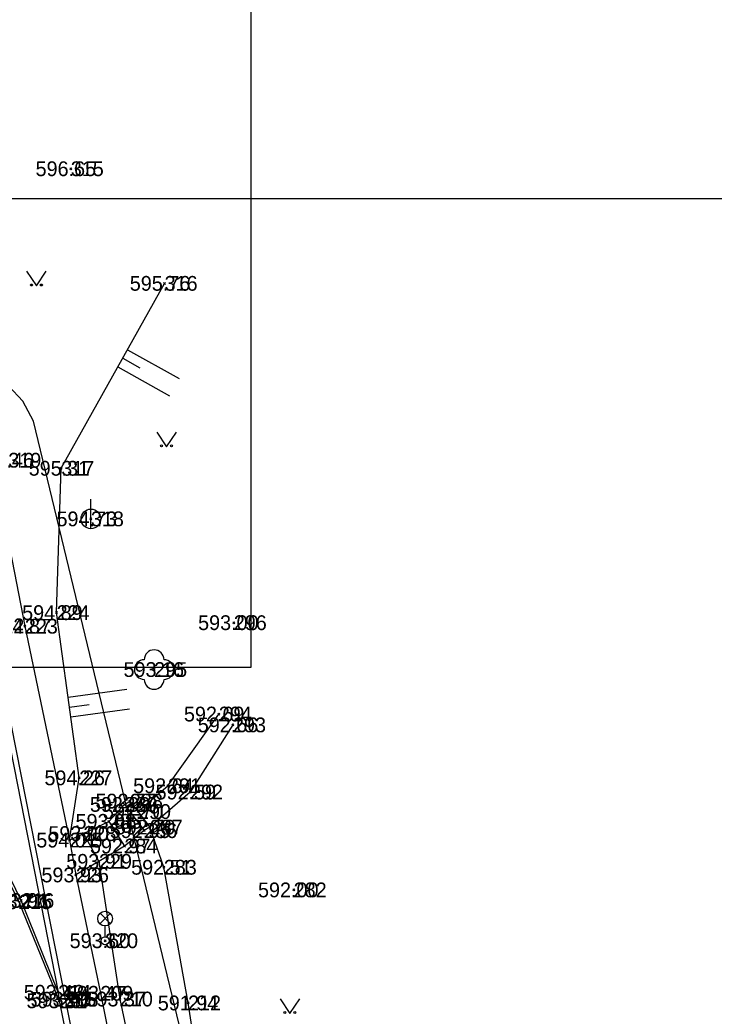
# Model space of a CAD drawing. Extents: x -844765 to -843273, y -997542 to -995529.
# Drawn here: x -843394.4 to -843359.2, y -997393 to -997342.4 of the extents above; entities that cross this region are included whole.
import ezdxf

# ---------------------------------------------------------------- set-up
doc = ezdxf.new("R2010")
doc.units = 0
for name, color, linetype in [('Betonový strop', 7, 'Continuous'), ('Dno', 7, 'Continuous'), ('Doplněk polohopisu', 7, 'Continuous'), ('Groma', 7, 'Continuous'), ('Osa', 7, 'Continuous'), ('Přítoky', 7, 'Continuous'), ('Sítě podzemní nerozlišené', 7, 'Continuous'), ('Vrstva 63', 7, 'Continuous'), ('Výškopis', 7, 'Continuous'), ('Číslo bodu', 7, 'Continuous'), ('Řezy', 7, 'Continuous')]:
    doc.layers.add(name, color=color, linetype=linetype)

msp = doc.modelspace()

# ---------------------------------------------------------------- linework, layer by layer
at = {"layer": 'Betonový strop'}
for points in [[(-843411.04, -997345.91), (-843412.15, -997348.62), (-843412.25, -997350.69), (-843411.88, -997353.72), (-843411.81, -997353.92), (-843411.14, -997356.34), (-843411.1, -997356.6), (-843409.66, -997360.3), (-843407.54, -997364.86), (-843405.52, -997368.28), (-843401.64, -997374.1), (-843397.84, -997380.36), (-843394.46, -997387.21), (-843392.42, -997392.24)], [(-843392.47, -997391.81), (-843394.34, -997387.15), (-843397.7, -997380.27), (-843401.51, -997374.02), (-843405.41, -997368.2), (-843407.39, -997364.76), (-843409.55, -997360.23), (-843410.95, -997356.55), (-843410.97, -997356.46), (-843411.8, -997353.57), (-843412.09, -997350.7), (-843412.01, -997348.64), (-843410.91, -997345.96)], [(-843399.61, -997355.89), (-843396.11, -997373.33), (-843392.47, -997391.81), (-843392.42, -997392.24), (-843388.24, -997412.76), (-843386.27, -997422.84), (-843384.29, -997432.84)], [(-843384.04, -997432.8), (-843386.03, -997422.75), (-843388, -997412.68), (-843392.09, -997392.16), (-843395.86, -997373.2), (-843399.33, -997355.86)], [(-843397.6, -997355.58), (-843394.16, -997373.22), (-843391.89, -997384.08), (-843391.57, -997385.85), (-843390.33, -997391.86), (-843386.25, -997412.31), (-843384.43, -997421.53), (-843384.06, -997423.53), (-843381.79, -997434.8)], [(-843388.42, -997382.63), (-843386.9, -997381.32), (-843384.32, -997377.68)], [(-843383.6, -997378.23), (-843385.78, -997381.64), (-843387.82, -997383.42)], [(-843389.9, -997383.13), (-843389.11, -997382.27), (-843388.1, -997383.6), (-843389.11, -997384.38)], [(-843389.11, -997382.27), (-843388.83, -997382.1), (-843388.42, -997382.63), (-843387.82, -997383.42), (-843388.1, -997383.6)], [(-843391.19, -997383.75), (-843389.9, -997383.13), (-843389.11, -997384.38), (-843390.4, -997385.16)], [(-843391.89, -997384.08), (-843391.19, -997383.75), (-843390.4, -997385.16), (-843391.57, -997385.85)]]:
    msp.add_lwpolyline(points, dxfattribs=at)
at = {"layer": 'Dno'}
for points in [[(-843394.073, -997355.193), (-843393.573, -997355.943), (-843393.073, -997355.193)], [(-843387.472, -997363.358), (-843386.972, -997364.108), (-843386.472, -997363.358)], [(-843381.214, -997392.138), (-843380.714, -997392.888), (-843380.214, -997392.138)]]:
    msp.add_lwpolyline(points, dxfattribs=at)
for centre in [(-843393.823, -997355.893), (-843393.323, -997355.893), (-843387.222, -997364.058), (-843386.722, -997364.058), (-843380.964, -997392.838), (-843380.464, -997392.838)]:
    msp.add_circle(centre, 0.05, dxfattribs=at)
at = {"layer": 'Doplněk polohopisu'}
msp.add_line((-843390.81, -997368.27), (-843390.81, -997366.77), dxfattribs=at)
msp.add_circle((-843390.81, -997367.77), 0.5, dxfattribs=at)
at = {"layer": 'Groma'}
for p, q in [((-843390.354, -997388.328), (-843389.826, -997387.8)), ((-843389.818, -997388.325), (-843390.346, -997387.796)), ((-843390.09, -997388.99), (-843390.09, -997388.44))]:
    msp.add_line(p, q, dxfattribs=at)
for centre, radius in [((-843390.09, -997388.065), 0.375), ((-843390.09, -997389.19), 0.2)]:
    msp.add_circle(centre, radius, dxfattribs=at)
at = {"layer": 'Osa'}
for points in [[(-843361.41, -997525.395), (-843362.635, -997520.015), (-843367.895, -997475.79), (-843371.92, -997453.18), (-843393.72, -997362.81), (-843394.265, -997361.8), (-843395.735, -997360.23), (-843405.12, -997356.145), (-843414.51, -997352.845), (-843426.28, -997348.668), (-843434.95, -997345.635), (-843447.93, -997341.273), (-843467.555, -997334.81), (-843481.31, -997330.35), (-843488.74, -997327.355), (-843502.42, -997320.345)], [(-843391.89, -997384.08), (-843391.4, -997380.92), (-843392.55, -997372.53), (-843392.31, -997365.2), (-843387.07, -997355.81)], [(-843381.18, -997422.62), (-843381.3, -997416.76), (-843383.02, -997410.78), (-843385.88, -997392.35), (-843387.11, -997385.46), (-843387.82, -997383.42)], [(-843390.4, -997385.16), (-843389.34, -997392.15), (-843385.2, -997411.73), (-843383.15, -997421.85)]]:
    msp.add_lwpolyline(points, dxfattribs=at)
at = {"layer": 'Přítoky'}
for p, q in [((-843388.95, -997359.178), (-843386.33, -997360.64)), ((-843389.193, -997359.615), (-843388.32, -997360.102)), ((-843389.437, -997360.052), (-843386.817, -997361.514)), ((-843391.961, -997376.829), (-843388.988, -997376.422)), ((-843391.893, -997377.325), (-843390.902, -997377.189)), ((-843391.825, -997377.82), (-843388.853, -997377.413))]:
    msp.add_line(p, q, dxfattribs=at)
at = {"layer": 'Sítě podzemní nerozlišené'}
for p, q in [((-843391.83, -997349.99), (-843391.88, -997349.94)), ((-843391.83, -997349.99), (-843391.88, -997350.04)), ((-843391.83, -997349.99), (-843391.78, -997349.94)), ((-843391.83, -997349.99), (-843391.78, -997350.04)), ((-843387.07, -997355.81), (-843387.12, -997355.76)), ((-843387.07, -997355.81), (-843387.12, -997355.86)), ((-843387.07, -997355.81), (-843387.02, -997355.76)), ((-843387.07, -997355.81), (-843387.02, -997355.86)), ((-843392.31, -997365.2), (-843392.36, -997365.15)), ((-843392.31, -997365.2), (-843392.36, -997365.25)), ((-843392.31, -997365.2), (-843392.26, -997365.15)), ((-843392.31, -997365.2), (-843392.26, -997365.25)), ((-843390.81, -997367.77), (-843390.86, -997367.72)), ((-843390.81, -997367.77), (-843390.86, -997367.82)), ((-843390.81, -997367.77), (-843390.76, -997367.72)), ((-843390.81, -997367.77), (-843390.76, -997367.82)), ((-843392.55, -997372.53), (-843392.6, -997372.48)), ((-843392.55, -997372.53), (-843392.6, -997372.58)), ((-843392.55, -997372.53), (-843392.5, -997372.48)), ((-843392.55, -997372.53), (-843392.5, -997372.58)), ((-843383.56, -997373.04), (-843383.61, -997372.99)), ((-843383.56, -997373.04), (-843383.61, -997373.09)), ((-843383.56, -997373.04), (-843383.51, -997372.99)), ((-843383.56, -997373.04), (-843383.51, -997373.09)), ((-843394.16, -997373.22), (-843394.21, -997373.17)), ((-843394.16, -997373.22), (-843394.21, -997373.27)), ((-843394.16, -997373.22), (-843394.11, -997373.17)), ((-843394.16, -997373.22), (-843394.11, -997373.27)), ((-843387.6, -997375.42), (-843387.65, -997375.37)), ((-843387.6, -997375.42), (-843387.65, -997375.47)), ((-843387.6, -997375.42), (-843387.55, -997375.37)), ((-843387.6, -997375.42), (-843387.55, -997375.47)), ((-843384.32, -997377.68), (-843384.37, -997377.63)), ((-843384.32, -997377.68), (-843384.37, -997377.73)), ((-843384.32, -997377.68), (-843384.27, -997377.63)), ((-843384.32, -997377.68), (-843384.27, -997377.73)), ((-843383.6, -997378.23), (-843383.65, -997378.18)), ((-843383.6, -997378.23), (-843383.55, -997378.18)), ((-843383.6, -997378.23), (-843383.65, -997378.28)), ((-843383.6, -997378.23), (-843383.55, -997378.28)), ((-843391.4, -997380.92), (-843391.45, -997380.87)), ((-843391.4, -997380.92), (-843391.45, -997380.97)), ((-843391.4, -997380.92), (-843391.35, -997380.87)), ((-843391.4, -997380.92), (-843391.35, -997380.97)), ((-843386.9, -997381.32), (-843386.95, -997381.27)), ((-843386.9, -997381.32), (-843386.95, -997381.37)), ((-843386.9, -997381.32), (-843386.85, -997381.27)), ((-843386.9, -997381.32), (-843386.85, -997381.37)), ((-843385.78, -997381.64), (-843385.83, -997381.59)), ((-843385.78, -997381.64), (-843385.83, -997381.69)), ((-843385.78, -997381.64), (-843385.73, -997381.59)), ((-843385.78, -997381.64), (-843385.73, -997381.69)), ((-843389.11, -997382.27), (-843389.16, -997382.22)), ((-843389.11, -997382.27), (-843389.16, -997382.32)), ((-843389.11, -997382.27), (-843389.06, -997382.22)), ((-843389.11, -997382.27), (-843389.06, -997382.32)), ((-843388.83, -997382.1), (-843388.88, -997382.05)), ((-843388.83, -997382.1), (-843388.88, -997382.15)), ((-843388.83, -997382.1), (-843388.78, -997382.05)), ((-843388.83, -997382.1), (-843388.78, -997382.15)), ((-843388.42, -997382.63), (-843388.47, -997382.58)), ((-843388.42, -997382.63), (-843388.47, -997382.68)), ((-843388.42, -997382.63), (-843388.37, -997382.58)), ((-843388.42, -997382.63), (-843388.37, -997382.68)), ((-843389.9, -997383.13), (-843389.95, -997383.08)), ((-843389.9, -997383.13), (-843389.95, -997383.18)), ((-843389.9, -997383.13), (-843389.85, -997383.08)), ((-843389.9, -997383.13), (-843389.85, -997383.18)), ((-843391.19, -997383.75), (-843391.24, -997383.7)), ((-843391.19, -997383.75), (-843391.24, -997383.8)), ((-843391.19, -997383.75), (-843391.14, -997383.7)), ((-843391.19, -997383.75), (-843391.14, -997383.8)), ((-843388.1, -997383.6), (-843388.15, -997383.55)), ((-843388.1, -997383.6), (-843388.15, -997383.65)), ((-843388.1, -997383.6), (-843388.05, -997383.55)), ((-843388.1, -997383.6), (-843388.05, -997383.65)), ((-843387.82, -997383.42), (-843387.87, -997383.37)), ((-843387.82, -997383.42), (-843387.87, -997383.47)), ((-843387.82, -997383.42), (-843387.77, -997383.37)), ((-843387.82, -997383.42), (-843387.77, -997383.47)), ((-843391.89, -997384.08), (-843391.94, -997384.03)), ((-843391.89, -997384.08), (-843391.94, -997384.13)), ((-843391.89, -997384.08), (-843391.84, -997384.03)), ((-843391.89, -997384.08), (-843391.84, -997384.13)), ((-843389.11, -997384.38), (-843389.16, -997384.33)), ((-843389.11, -997384.38), (-843389.16, -997384.43)), ((-843389.11, -997384.38), (-843389.06, -997384.33)), ((-843389.11, -997384.38), (-843389.06, -997384.43)), ((-843390.4, -997385.16), (-843390.45, -997385.11)), ((-843390.4, -997385.16), (-843390.45, -997385.21)), ((-843390.4, -997385.16), (-843390.35, -997385.11)), ((-843390.4, -997385.16), (-843390.35, -997385.21)), ((-843391.57, -997385.85), (-843391.62, -997385.8)), ((-843391.57, -997385.85), (-843391.52, -997385.8)), ((-843387.11, -997385.46), (-843387.16, -997385.41)), ((-843387.11, -997385.46), (-843387.16, -997385.51)), ((-843387.11, -997385.46), (-843387.06, -997385.41)), ((-843387.11, -997385.46), (-843387.06, -997385.51)), ((-843391.57, -997385.85), (-843391.62, -997385.9)), ((-843391.57, -997385.85), (-843391.52, -997385.9)), ((-843380.52, -997386.61), (-843380.57, -997386.56)), ((-843380.52, -997386.61), (-843380.57, -997386.66)), ((-843380.52, -997386.61), (-843380.47, -997386.56)), ((-843380.52, -997386.61), (-843380.47, -997386.66)), ((-843394.34, -997387.15), (-843394.39, -997387.1)), ((-843394.34, -997387.15), (-843394.39, -997387.2)), ((-843394.34, -997387.15), (-843394.29, -997387.1)), ((-843394.34, -997387.15), (-843394.29, -997387.2)), ((-843390.09, -997389.19), (-843390.14, -997389.14)), ((-843390.09, -997389.19), (-843390.14, -997389.24)), ((-843390.09, -997389.19), (-843390.04, -997389.14)), ((-843390.09, -997389.19), (-843390.04, -997389.24)), ((-843392.47, -997391.81), (-843392.52, -997391.76)), ((-843392.47, -997391.81), (-843392.52, -997391.86)), ((-843392.47, -997391.81), (-843392.42, -997391.76)), ((-843392.47, -997391.81), (-843392.42, -997391.86)), ((-843390.33, -997391.86), (-843390.38, -997391.81)), ((-843390.33, -997391.86), (-843390.38, -997391.91)), ((-843390.33, -997391.86), (-843390.28, -997391.81)), ((-843390.33, -997391.86), (-843390.28, -997391.91)), ((-843392.42, -997392.24), (-843392.47, -997392.19)), ((-843392.42, -997392.24), (-843392.47, -997392.29)), ((-843392.42, -997392.24), (-843392.37, -997392.19)), ((-843392.42, -997392.24), (-843392.37, -997392.29)), ((-843392.09, -997392.16), (-843392.14, -997392.11)), ((-843392.09, -997392.16), (-843392.14, -997392.21)), ((-843392.09, -997392.16), (-843392.04, -997392.11)), ((-843392.09, -997392.16), (-843392.04, -997392.21)), ((-843389.34, -997392.15), (-843389.39, -997392.1)), ((-843389.34, -997392.15), (-843389.39, -997392.2)), ((-843389.34, -997392.15), (-843389.29, -997392.1)), ((-843389.34, -997392.15), (-843389.29, -997392.2)), ((-843385.88, -997392.35), (-843385.93, -997392.3)), ((-843385.88, -997392.35), (-843385.93, -997392.4)), ((-843385.88, -997392.35), (-843385.83, -997392.3)), ((-843385.88, -997392.35), (-843385.83, -997392.4))]:
    msp.add_line(p, q, dxfattribs=at)
at = {"layer": 'Vrstva 63'}
for points in [[(-843572.683, -997375.3), (-843382.683, -997375.3), (-843382.683, -997232.8), (-843572.683, -997232.8)], [(-843273.067, -997541.514), (-843273.067, -997351.514), (-843415.567, -997351.514), (-843415.567, -997541.514)]]:
    msp.add_lwpolyline(points, close=True, dxfattribs=at)
at = {"layer": 'Výškopis'}
msp.add_circle((-843387.6, -997375.42), 0.0005, dxfattribs=at)
for centre, start, end in [((-843387.6, -997374.92), 0, 180), ((-843388.1, -997375.42), 90, 270), ((-843387.1, -997375.42), 270, 90), ((-843387.6, -997375.92), 180, 360)]:
    msp.add_arc(centre, 0.5, start, end, dxfattribs=at)

# ---------------------------------------------------------------- texts
at = {"layer": 'Číslo bodu'}
for s, p in [('315', (-843391.83, -997350.365)), ('316', (-843387.07, -997356.185)), ('319', (-843395, -997365.165)), ('317', (-843392.31, -997365.575)), ('318', (-843390.81, -997368.145)), ('224', (-843392.55, -997372.905)), ('296', (-843383.56, -997373.415)), ('222', (-843395.86, -997373.575)), ('223', (-843394.16, -997373.595)), ('295', (-843387.6, -997375.795)), ('294', (-843384.32, -997378.055)), ('293', (-843383.6, -997378.605)), ('227', (-843391.4, -997381.295)), ('291', (-843386.9, -997381.695)), ('292', (-843385.78, -997382.015)), ('288', (-843388.83, -997382.475)), ('289', (-843389.11, -997382.645)), ('290', (-843388.42, -997383.005)), ('285', (-843389.9, -997383.505)), ('286', (-843388.1, -997383.975)), ('287', (-843387.82, -997383.795)), ('225', (-843391.89, -997384.455)), ('228', (-843391.19, -997384.125)), ('284', (-843389.11, -997384.755)), ('229', (-843390.4, -997385.535)), ('283', (-843387.11, -997385.835)), ('226', (-843391.57, -997386.225)), ('282', (-843380.52, -997386.985)), ('216', (-843394.34, -997387.525)), ('215', (-843394.46, -997387.585)), ('320', (-843390.09, -997389.565)), ('214', (-843392.47, -997392.185)), ('207', (-843392.42, -997392.615)), ('208', (-843392.09, -997392.535)), ('209', (-843390.33, -997392.235)), ('210', (-843389.34, -997392.525)), ('212', (-843385.88, -997392.725))]:
    msp.add_text(s, height=0.75, dxfattribs=at).set_placement(p)
at = {"layer": 'Řezy'}
for s, p in [('596.65', (-843393.616, -997350.365)), ('595.76', (-843388.836, -997356.185)), ('595.46', (-843396.766, -997365.165)), ('595.31', (-843393.966, -997365.575)), ('594.73', (-843392.555, -997368.145)), ('594.89', (-843394.298, -997372.905)), ('593.00', (-843385.37, -997373.415)), ('594.87', (-843395.905, -997373.595)), ('593.16', (-843389.153, -997375.795)), ('592.69', (-843386.089, -997378.055)), ('592.66', (-843385.386, -997378.605)), ('594.26', (-843393.166, -997381.295)), ('592.64', (-843388.666, -997381.695)), ('592.59', (-843387.528, -997382.015)), ('592.77', (-843390.575, -997382.475)), ('592.99', (-843390.861, -997382.645)), ('592.70', (-843390.197, -997383.005)), ('593.01', (-843391.589, -997383.505)), ('592.95', (-843389.848, -997383.975)), ('592.70', (-843389.597, -997383.795)), ('594.01', (-843393.579, -997384.455)), ('593.90', (-843392.97, -997384.125)), ('592.97', (-843390.858, -997384.755)), ('593.91', (-843392.059, -997385.535)), ('592.51', (-843388.766, -997385.835)), ('593.93', (-843393.318, -997386.225)), ('592.00', (-843382.33, -997386.985)), ('593.91', (-843395.999, -997387.525)), ('593.77', (-843396.205, -997387.585)), ('593.60', (-843391.888, -997389.565)), ('593.43', (-843394.215, -997392.185)), ('593.31', (-843394.076, -997392.615)), ('593.40', (-843393.867, -997392.535)), ('593.47', (-843392.075, -997392.235)), ('593.37', (-843391.085, -997392.525)), ('591.94', (-843387.415, -997392.725))]:
    msp.add_text(s, height=0.75, dxfattribs=at).set_placement(p)

doc.saveas('drawing.dxf')
